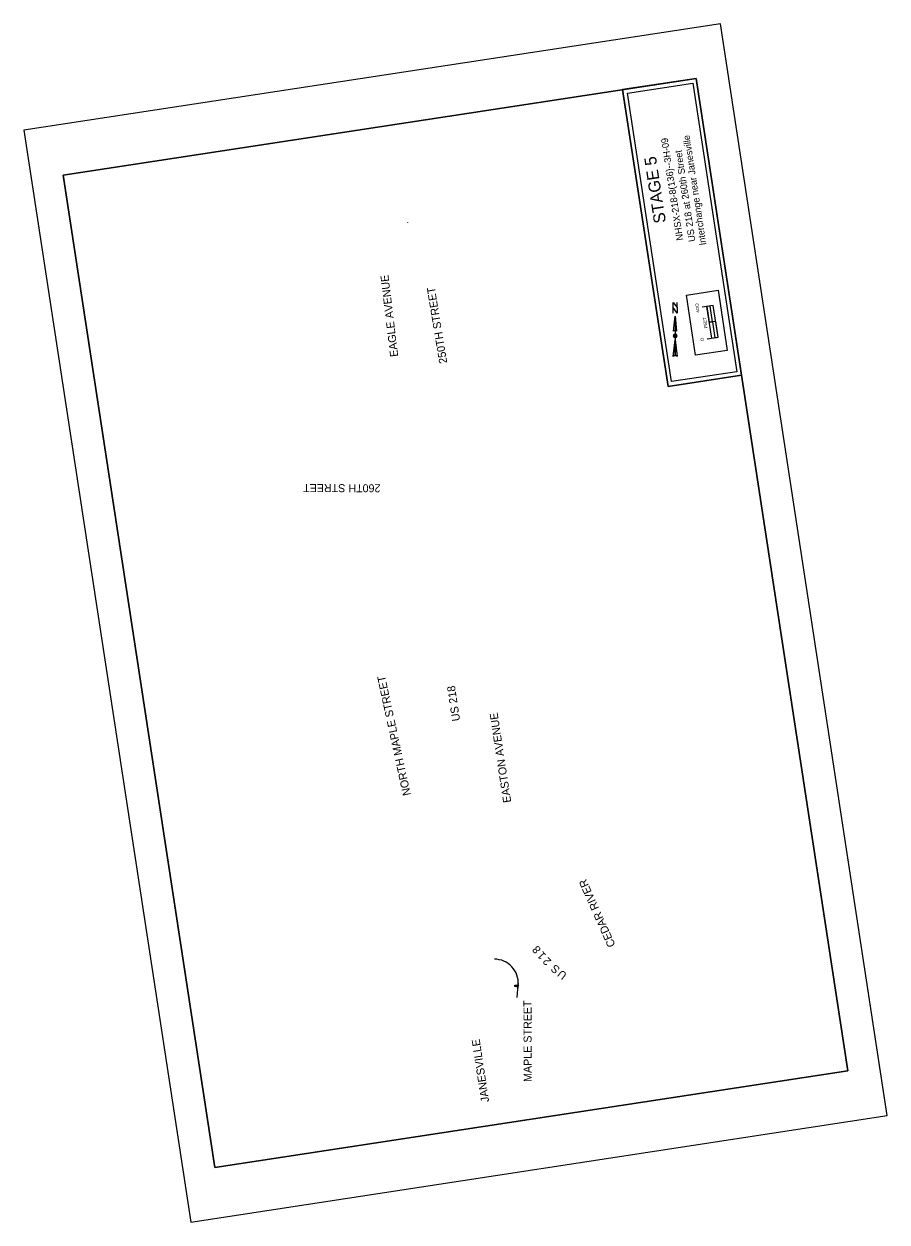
# Model space of a CAD drawing. Extents: x 5192026 to 5202808, y 3700291 to 3715256.
import ezdxf

# ---------------------------------------------------------------- set-up
doc = ezdxf.new("R2010")
doc.units = 0
for name, color, linetype in [('Cell', 7, 'Continuous'), ('Draft_9', 7, 'Continuous'), ('Drainage', 7, 'Continuous'), ('EdgePaved', 7, 'Continuous'), ('NamedBoundary', 7, 'Continuous'), ('Shape', 7, 'Continuous'), ('SheetBorder', 7, 'Continuous'), ('SheetText', 7, 'Continuous')]:
    doc.layers.add(name, color=color, linetype=linetype)

msp = doc.modelspace()

# ---------------------------------------------------------------- linework, layer by layer
at = {"layer": 'Cell'}
for p, q in [((5200161, 3711607), (5200180, 3711417)), ((5200161, 3711607), (5200161, 3711113)), ((5200142, 3711419), (5200146, 3711423)), ((5200142, 3711417), (5200142, 3711417)), ((5200161, 3711336), (5200161, 3711336)), ((5200137, 3711103), (5200161, 3711312))]:
    msp.add_line(p, q, dxfattribs=at)
msp.add_lwpolyline([(5200185, 3711645), (5200137, 3711712), (5200137, 3711778), (5200185, 3711712)], close=True, dxfattribs=at)
for points in [[(5200137, 3711645), (5200137, 3711778), (5200185, 3711712), (5200185, 3711778)], [(5200142, 3711417), (5200161, 3711607), (5200161, 3711426)], [(5200161, 3711336), (5200161, 3711360), (5200137, 3711360)], [(5200185, 3711360), (5200161, 3711360), (5200161, 3711384)], [(5200161, 3711113), (5200161, 3711312), (5200185, 3711103)]]:
    msp.add_lwpolyline(points, dxfattribs=at)
for centre, radius, start, end in [((5200161, 3711360), 23.8, 90, 180), ((5200161, 3711360), 23.8, 180, 270), ((5200161, 3711403), 23.8, 90.0204, 143.1257), ((5200161, 3711403), 23.8, 36.8481, 90.0218), ((5200161, 3711360), 23.8, 0, 90), ((5200161, 3711360), 23.8, 270, 360), ((5200161, 3711078), 34.4, 89.9894, 133.619), ((5200161, 3711078), 34.5, 46.4021, 90.0006)]:
    msp.add_arc(centre, radius, start, end, dxfattribs=at)
at = {"layer": 'Draft_9'}
for q in [(5196823, 3712774), (5196823, 3712770)]:
    msp.add_line((5196823, 3712770), q, dxfattribs=at)
at = {"layer": 'Drainage'}
for p, q in [((5198158, 3703248), (5198186, 3703250)), ((5198158, 3703248), (5198186, 3703250)), ((5198159, 3703231), (5198158, 3703248)), ((5198159, 3703231), (5198158, 3703248)), ((5198186, 3703094), (5198200, 3703254)), ((5198186, 3703094), (5198200, 3703254)), ((5198197, 3703220), (5198200, 3703257)), ((5198200, 3703257), (5198197, 3703220)), ((5198182, 3703229), (5198159, 3703231))]:
    msp.add_line(p, q, dxfattribs=at)
for centre, radius, start, end in [((5197906, 3703279), 295, 355.0831, 90.5978), ((5198185, 3703270), 20, 272.8175, 358.0701), ((5198185, 3703270), 20, 272.8175, 358.0701), ((5198180, 3703209), 20, 355.0839, 84.4202)]:
    msp.add_arc(centre, radius, start, end, dxfattribs=at)
at = {"layer": 'NamedBoundary'}
for points in [[(5194109, 3700291), (5202808, 3701620), (5200726, 3715256), (5192026, 3713927)], [(5194410, 3700971), (5202318, 3702179), (5200425, 3714575), (5192516, 3713368)]]:
    msp.add_lwpolyline(points, close=True, dxfattribs=at)
at = {"layer": 'Shape'}
for points in [[(5200072, 3710728), (5199505, 3714435), (5200425, 3714575), (5200991, 3710868)], [(5200116, 3710788), (5199566, 3714391), (5200381, 3714515), (5200931, 3710912)]]:
    msp.add_lwpolyline(points, close=True, dxfattribs=at)
for points in [[(5200991, 3710868), (5200425, 3714575), (5199505, 3714435), (5200072, 3710728), (5200991, 3710868)], [(5200116, 3710788), (5199566, 3714391), (5200381, 3714515), (5200931, 3710912), (5200116, 3710788)]]:
    msp.add_lwpolyline(points, dxfattribs=at)
at = {"layer": 'SheetBorder'}
msp.add_lwpolyline([(5194410, 3700971), (5192516, 3713368), (5200425, 3714575), (5202318, 3702179)], close=True, dxfattribs=at)
at = {"layer": 'SheetText'}
msp.add_line((5200668, 3711541), (5200588, 3711529), dxfattribs=at)
msp.add_line((5200668, 3711541), (5200588, 3711529), dxfattribs=at)
for points in [[(5200416, 3711118), (5200302, 3711869), (5200697, 3711930), (5200812, 3711178)], [(5200812, 3711178), (5200416, 3711118), (5200302, 3711869), (5200697, 3711930)], [(5200628, 3711535), (5200597, 3711732), (5200558, 3711726), (5200588, 3711529)], [(5200698, 3711343), (5200668, 3711541), (5200628, 3711535), (5200658, 3711337)]]:
    msp.add_lwpolyline(points, close=True, dxfattribs=at)
for points in [[(5200559, 3711322), (5200698, 3711343), (5200637, 3711739), (5200499, 3711717)], [(5200619, 3711331), (5200558, 3711726)]]:
    msp.add_lwpolyline(points, dxfattribs=at)

# ---------------------------------------------------------------- texts
at = {"layer": 'EdgePaved'}
msp.add_text('STAGE 5', height=148.9, rotation=98.6831, dxfattribs=at).set_placement((5200047, 3712778))
at = {"layer": 'SheetBorder'}
for s, rotation, p in [('EAGLE AVENUE', 96.8932, (5196702, 3711103)), ('250TH STREET', 99.3981, (5197315, 3711022)), ('260TH STREET', 179.8345, (5196480, 3709506)), ('NORTH MAPLE STREET', 102.2339, (5196860, 3705628)), ('US 218', 98.6831, (5197476, 3706555)), ('EASTON AVENUE', 98.6831, (5198114, 3705536)), ('CEDAR RIVER', 114.0562, (5199418, 3703750)), ('8', 129.328, (5198491, 3703695)), ('1', 131.4754, (5198554, 3703624)), ('2', 134.1916, (5198621, 3703555)), ('S', 139.0446, (5198730, 3703458)), ('U', 141.745, (5198817, 3703388)), ('MAPLE STREET', 90.1417, (5198369, 3702041)), ('JANESVILLE', 98.6831, (5197838, 3701796))]:
    msp.add_text(s, height=100, rotation=rotation, dxfattribs=at).set_placement(p)
at = {"layer": 'SheetText'}
for s, height, p in [('NHSX-218-8(136)--3H-09', 85, (5200263, 3712557)), ('Interchange near Janesville', 85, (5200551, 3712498)), ('  US 218 at 260th Street ', 85, (5200425, 3712479)), ('4OO', 40, (5200468, 3711653)), ('FEET', 40, (5200567, 3711457)), ('O', 40, (5200523, 3711296)), ('O', 40, (5200523, 3711296))]:
    msp.add_text(s, height=height, rotation=98.6831, dxfattribs=at).set_placement(p)

doc.saveas('drawing.dxf')
